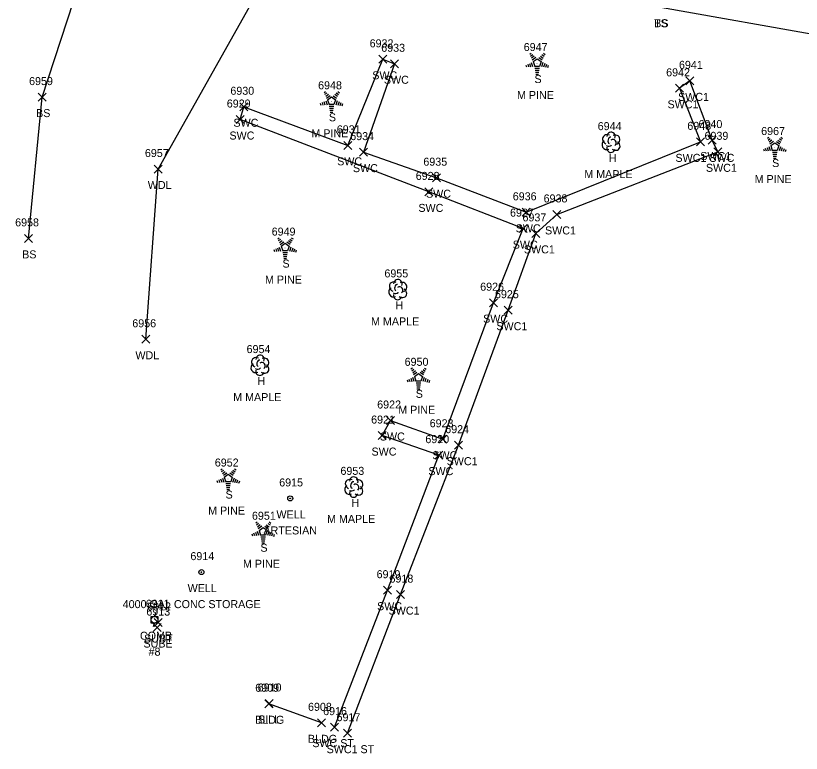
# Model space of a CAD drawing. Extents: x 1678863 to 1683592, y 407783 to 418211.
# Drawn here: x 1680420 to 1680616.3, y 408813.2 to 408997.5 of the extents above; entities that cross this region are included whole.
import ezdxf

# ---------------------------------------------------------------- set-up
doc = ezdxf.new("R2010")
doc.units = 0
for name, color, linetype in [('L_A', 7, 'Continuous'), ('L_C', 7, 'Continuous'), ('L_I', 7, 'Continuous'), ('L_TIC', 7, 'Continuous'), ('LAWA', 7, 'Continuous'), ('LBC', 7, 'Continuous'), ('LELB', 7, 'Continuous'), ('LTC', 7, 'Continuous'), ('LTD', 7, 'Continuous'), ('R_A', 7, 'Continuous'), ('R_I', 7, 'Continuous'), ('R_TIC', 7, 'Continuous'), ('RSW', 7, 'Continuous'), ('U_A', 7, 'Continuous'), ('U_C', 7, 'Continuous'), ('U_I', 7, 'Continuous'), ('U_TIC', 7, 'Continuous'), ('UP', 7, 'Continuous'), ('UWW', 7, 'Continuous')]:
    doc.layers.add(name, color=color, linetype=linetype)

msp = doc.modelspace()

# ---------------------------------------------------------------- linework, layer by layer
at = {"layer": 'L_TIC'}
for points in [[(1680425.67, 408976.2), (1680427.67, 408978.2)], [(1680427.67, 408976.2), (1680425.67, 408978.2)], [(1680454.61, 408958.22), (1680456.61, 408960.22)], [(1680456.61, 408958.22), (1680454.61, 408960.22)], [(1680422.19, 408940.88), (1680424.19, 408942.88)], [(1680424.19, 408940.88), (1680422.19, 408942.88)], [(1680451.51, 408915.66), (1680453.51, 408917.66)], [(1680453.51, 408915.66), (1680451.51, 408917.66)], [(1680482.26, 408824.55), (1680484.26, 408826.55)], [(1680484.26, 408824.55), (1680482.26, 408826.55)], [(1680482.32, 408824.63), (1680484.32, 408826.63)], [(1680484.32, 408824.63), (1680482.32, 408826.63)], [(1680495.45, 408819.79), (1680497.45, 408821.79)], [(1680497.45, 408819.79), (1680495.45, 408821.79)]]:
    msp.add_lwpolyline(points, dxfattribs=at)
at = {"layer": 'LAWA'}
msp.add_lwpolyline([(1680452.51, 408916.66), (1680455.61, 408959.22), (1680491.22, 409022.49)], dxfattribs=at)
at = {"layer": 'LBC'}
msp.add_lwpolyline([(1680496.45, 408820.79), (1680483.26, 408825.55)], dxfattribs=at)
at = {"layer": 'LELB'}
for points in [[(1680581.13, 408999.66), (1680622.52, 408992.36), (1680648.86, 408995.44), (1680697.24, 409002.73), (1680736.42, 409011.41), (1680777.65, 409017.22)], [(1680423.19, 408941.88), (1680426.67, 408977.2), (1680439.17, 409015.64)]]:
    msp.add_lwpolyline(points, dxfattribs=at)
at = {"layer": 'LTC'}
for p, q in [((1680548.46, 408987.92), (1680548.82, 408988.18)), ((1680548.67, 408987.45), (1680549.2, 408987.84)), ((1680548.88, 408986.99), (1680549.58, 408987.5)), ((1680549.09, 408986.52), (1680549.97, 408987.16)), ((1680549.31, 408986.07), (1680550.33, 408986.8)), ((1680550.33, 408986.8), (1680551.32, 408986.08)), ((1680550.75, 408987.12), (1680551.56, 408986.53)), ((1680551.12, 408987.46), (1680551.8, 408986.97)), ((1680551.49, 408987.81), (1680552.04, 408987.41)), ((1680551.86, 408988.16), (1680552.28, 408987.86)), ((1680547.49, 408985.2), (1680547.65, 408984.73)), ((1680547.95, 408985.42), (1680548.16, 408984.76)), ((1680548.4, 408985.63), (1680548.68, 408984.8)), ((1680548.86, 408985.85), (1680549.19, 408984.83)), ((1680549.31, 408986.07), (1680549.7, 408984.87)), ((1680550.93, 408984.87), (1680549.7, 408984.87)), ((1680550.89, 408984.37), (1680549.75, 408984.37)), ((1680551.32, 408986.08), (1680550.93, 408984.87)), ((1680551.76, 408985.81), (1680551.42, 408984.77)), ((1680552.21, 408985.56), (1680551.92, 408984.67)), ((1680552.65, 408985.31), (1680552.41, 408984.58)), ((1680553.09, 408985.06), (1680552.91, 408984.48)), ((1680550.81, 408983.87), (1680549.82, 408983.87)), ((1680550.73, 408983.37), (1680549.89, 408983.37)), ((1680550.64, 408982.87), (1680549.97, 408982.87)), ((1680497.08, 408978.36), (1680497.43, 408978.62)), ((1680500.48, 408978.6), (1680500.9, 408978.29)), ((1680497.29, 408977.89), (1680497.82, 408978.28)), ((1680497.5, 408977.43), (1680498.2, 408977.94)), ((1680497.71, 408976.96), (1680498.59, 408977.6)), ((1680497.93, 408976.51), (1680498.94, 408977.24)), ((1680497.93, 408976.51), (1680498.32, 408975.31)), ((1680498.94, 408977.24), (1680499.94, 408976.52)), ((1680499.36, 408977.55), (1680500.17, 408976.96)), ((1680499.94, 408976.52), (1680499.55, 408975.31)), ((1680499.73, 408977.9), (1680500.41, 408977.41)), ((1680500.11, 408978.25), (1680500.65, 408977.85)), ((1680496.11, 408975.64), (1680496.26, 408975.17)), ((1680496.57, 408975.85), (1680496.78, 408975.2)), ((1680497.02, 408976.07), (1680497.29, 408975.24)), ((1680497.48, 408976.29), (1680497.81, 408975.27)), ((1680499.55, 408975.31), (1680498.32, 408975.31)), ((1680499.51, 408974.81), (1680498.37, 408974.81)), ((1680500.38, 408976.24), (1680500.04, 408975.21)), ((1680500.82, 408975.99), (1680500.53, 408975.11)), ((1680501.27, 408975.74), (1680501.03, 408975.01)), ((1680501.71, 408975.49), (1680501.52, 408974.92)), ((1680499.43, 408974.31), (1680498.44, 408974.31)), ((1680499.34, 408973.81), (1680498.51, 408973.81)), ((1680499.26, 408973.31), (1680498.58, 408973.31)), ((1680607.84, 408966.92), (1680608.19, 408967.17)), ((1680608.05, 408966.45), (1680608.58, 408966.84)), ((1680610.87, 408966.81), (1680611.41, 408966.41)), ((1680611.24, 408967.16), (1680611.66, 408966.85)), ((1680608.24, 408964.85), (1680608.57, 408963.83)), ((1680608.26, 408965.99), (1680608.96, 408966.5)), ((1680608.47, 408965.52), (1680609.35, 408966.16)), ((1680608.69, 408965.06), (1680609.7, 408965.8)), ((1680608.69, 408965.06), (1680609.08, 408963.87)), ((1680609.7, 408965.8), (1680610.7, 408965.07)), ((1680610.12, 408966.11), (1680610.93, 408965.52)), ((1680610.7, 408965.07), (1680610.31, 408963.87)), ((1680610.49, 408966.46), (1680611.17, 408965.97)), ((1680611.14, 408964.8), (1680610.8, 408963.76)), ((1680606.87, 408964.2), (1680607.02, 408963.73)), ((1680607.33, 408964.41), (1680607.54, 408963.76)), ((1680607.78, 408964.63), (1680608.05, 408963.79)), ((1680610.31, 408963.87), (1680609.08, 408963.87)), ((1680610.27, 408963.37), (1680609.13, 408963.37)), ((1680610.19, 408962.87), (1680609.2, 408962.87)), ((1680611.58, 408964.55), (1680611.29, 408963.67)), ((1680612.03, 408964.3), (1680611.79, 408963.57)), ((1680612.47, 408964.05), (1680612.28, 408963.48)), ((1680610.1, 408962.37), (1680609.27, 408962.37)), ((1680610.02, 408961.87), (1680609.34, 408961.87)), ((1680485.49, 408941.79), (1680485.85, 408942.05)), ((1680485.7, 408941.32), (1680486.23, 408941.71)), ((1680485.91, 408940.86), (1680486.62, 408941.37)), ((1680488.15, 408941.33), (1680488.83, 408940.84)), ((1680488.52, 408941.68), (1680489.07, 408941.28)), ((1680488.89, 408942.03), (1680489.31, 408941.73)), ((1680484.98, 408939.29), (1680485.19, 408938.63)), ((1680485.44, 408939.5), (1680485.71, 408938.67)), ((1680485.89, 408939.72), (1680486.22, 408938.7)), ((1680486.12, 408940.39), (1680487, 408941.03)), ((1680486.35, 408939.94), (1680487.36, 408940.67)), ((1680486.35, 408939.94), (1680486.73, 408938.74)), ((1680487.36, 408940.67), (1680488.35, 408939.95)), ((1680487.78, 408940.98), (1680488.59, 408940.4)), ((1680488.35, 408939.95), (1680487.96, 408938.74)), ((1680488.79, 408939.68), (1680488.45, 408938.64)), ((1680489.24, 408939.43), (1680488.95, 408938.54)), ((1680484.53, 408939.07), (1680484.68, 408938.6)), ((1680487.96, 408938.74), (1680486.73, 408938.74)), ((1680487.93, 408938.24), (1680486.78, 408938.24)), ((1680487.84, 408937.74), (1680486.85, 408937.74)), ((1680487.76, 408937.24), (1680486.93, 408937.24)), ((1680489.68, 408939.18), (1680489.44, 408938.45)), ((1680490.13, 408938.93), (1680489.94, 408938.35)), ((1680487.67, 408936.74), (1680487, 408936.74)), ((1680518.79, 408909.24), (1680519.14, 408909.49)), ((1680519, 408908.77), (1680519.53, 408909.15)), ((1680519.21, 408908.3), (1680519.91, 408908.82)), ((1680519.42, 408907.84), (1680520.29, 408908.48)), ((1680519.64, 408907.38), (1680520.65, 408908.12)), ((1680520.65, 408908.12), (1680521.65, 408907.39)), ((1680521.07, 408908.43), (1680521.88, 408907.84)), ((1680521.44, 408908.78), (1680522.12, 408908.29)), ((1680521.81, 408909.13), (1680522.36, 408908.73)), ((1680522.19, 408909.48), (1680522.61, 408909.17)), ((1680517.82, 408906.51), (1680517.97, 408906.05)), ((1680518.28, 408906.73), (1680518.49, 408906.08)), ((1680518.73, 408906.95), (1680519, 408906.11)), ((1680519.19, 408907.16), (1680519.52, 408906.15)), ((1680519.64, 408907.38), (1680520.03, 408906.19)), ((1680521.26, 408906.19), (1680520.03, 408906.19)), ((1680521.65, 408907.39), (1680521.26, 408906.19)), ((1680522.09, 408907.12), (1680521.75, 408906.08)), ((1680522.53, 408906.87), (1680522.24, 408905.99)), ((1680522.98, 408906.62), (1680522.74, 408905.89)), ((1680523.42, 408906.37), (1680523.23, 408905.8)), ((1680521.22, 408905.69), (1680520.08, 408905.69)), ((1680521.14, 408905.19), (1680520.15, 408905.19)), ((1680521.05, 408904.69), (1680520.22, 408904.69)), ((1680520.97, 408904.19), (1680520.29, 408904.19)), ((1680471.27, 408884.06), (1680471.63, 408884.31)), ((1680474.67, 408884.3), (1680475.09, 408883.99)), ((1680471.48, 408883.59), (1680472.01, 408883.97)), ((1680471.69, 408883.12), (1680472.39, 408883.64)), ((1680471.9, 408882.66), (1680472.78, 408883.3)), ((1680472.12, 408882.2), (1680473.14, 408882.94)), ((1680473.14, 408882.94), (1680474.13, 408882.21)), ((1680473.56, 408883.25), (1680474.37, 408882.66)), ((1680473.93, 408883.6), (1680474.61, 408883.11)), ((1680474.3, 408883.95), (1680474.85, 408883.55)), ((1680470.3, 408881.33), (1680470.46, 408880.87)), ((1680470.76, 408881.55), (1680470.97, 408880.9)), ((1680471.21, 408881.77), (1680471.49, 408880.93)), ((1680471.67, 408881.98), (1680472, 408880.97)), ((1680472.12, 408882.2), (1680472.51, 408881.01)), ((1680473.74, 408881.01), (1680472.51, 408881.01)), ((1680473.7, 408880.51), (1680472.56, 408880.51)), ((1680474.13, 408882.21), (1680473.74, 408881.01)), ((1680474.57, 408881.94), (1680474.23, 408880.9)), ((1680475.02, 408881.69), (1680474.73, 408880.81)), ((1680475.46, 408881.44), (1680475.22, 408880.71)), ((1680475.9, 408881.19), (1680475.72, 408880.62)), ((1680473.62, 408880.01), (1680472.63, 408880.01)), ((1680473.54, 408879.51), (1680472.7, 408879.51)), ((1680473.45, 408879.01), (1680472.78, 408879.01)), ((1680479.98, 408870.75), (1680480.34, 408871.01)), ((1680480.19, 408870.29), (1680480.72, 408870.67)), ((1680483.01, 408870.65), (1680483.56, 408870.25)), ((1680483.38, 408870.99), (1680483.8, 408870.69)), ((1680480.38, 408868.68), (1680480.71, 408867.66)), ((1680480.4, 408869.82), (1680481.1, 408870.33)), ((1680480.61, 408869.36), (1680481.49, 408869.99)), ((1680480.83, 408868.9), (1680481.85, 408869.64)), ((1680480.83, 408868.9), (1680481.22, 408867.71)), ((1680481.85, 408869.64), (1680482.84, 408868.91)), ((1680482.27, 408869.95), (1680483.08, 408869.36)), ((1680482.84, 408868.91), (1680482.45, 408867.71)), ((1680482.64, 408870.3), (1680483.32, 408869.8)), ((1680483.28, 408868.64), (1680482.94, 408867.6)), ((1680479.01, 408868.03), (1680479.17, 408867.57)), ((1680479.47, 408868.25), (1680479.68, 408867.6)), ((1680479.92, 408868.47), (1680480.2, 408867.63)), ((1680482.45, 408867.71), (1680481.22, 408867.71)), ((1680482.41, 408867.21), (1680481.27, 408867.21)), ((1680482.33, 408866.71), (1680481.34, 408866.71)), ((1680483.72, 408868.39), (1680483.44, 408867.51)), ((1680484.17, 408868.14), (1680483.93, 408867.41)), ((1680484.61, 408867.89), (1680484.43, 408867.32)), ((1680482.25, 408866.21), (1680481.41, 408866.21)), ((1680482.16, 408865.71), (1680481.49, 408865.71))]:
    msp.add_line(p, q, dxfattribs=at)
at = {"layer": 'LTD'}
for p, q in [((1680568.75, 408965.94), (1680568.75, 408965.94)), ((1680568.75, 408965.94), (1680568.75, 408965.94)), ((1680515.46, 408929.13), (1680515.46, 408929.13)), ((1680515.46, 408929.13), (1680515.46, 408929.13)), ((1680481.02, 408910.21), (1680481.02, 408910.21)), ((1680481.02, 408910.21), (1680481.02, 408910.21)), ((1680504.47, 408879.77), (1680504.47, 408879.77)), ((1680504.47, 408879.77), (1680504.47, 408879.77))]:
    msp.add_line(p, q, dxfattribs=at)
for centre in [(1680568.8, 408967.38), (1680515.51, 408930.56), (1680481.07, 408911.65), (1680504.51, 408881.2)]:
    msp.add_arc(centre, 1.05, 335.5272, 180.9563, dxfattribs=at)
for centre, major_axis, ratio, start_param, end_param in [((1680567.96, 408966.61), (1.21, -0.51), 0.895232, 1.570796, 4.712389), ((1680568.54, 408966.4), (-0.208, -0.792), 0.645439, 3.141593, 6.283185), ((1680569.25, 408965.78), (-0.5, 0.667), 0.989748, 3.141593, 6.283185), ((1680569.79, 408966.53), (-1.14, -0.48), 0.949671, 1.570796, 4.712389), ((1680567.67, 408965.24), (0.58, -1.04), 0.959034, 3.141593, 6.283185), ((1680568.29, 408965.19), (-0.625, -0.083), 0.423636, 0, 3.141593), ((1680569.75, 408965.11), (-1.09, 0.79), 0.841452, 1.570796, 4.712389), ((1680568.75, 408964.44), (0.26, 1.06), 0.942809, 1.570796, 4.712389), ((1680514.38, 408928.42), (0.58, -1.04), 0.959034, 3.141593, 6.283185), ((1680514.67, 408929.8), (1.21, -0.51), 0.895232, 1.570796, 4.712389), ((1680515.25, 408929.59), (-0.208, -0.792), 0.645439, 3.141593, 6.283185), ((1680515.96, 408928.96), (-0.5, 0.667), 0.989748, 3.141593, 6.283185), ((1680516.5, 408929.71), (-1.14, -0.48), 0.949671, 1.570796, 4.712389), ((1680515.46, 408927.63), (0.26, 1.06), 0.942809, 1.570796, 4.712389), ((1680515, 408928.38), (-0.625, -0.083), 0.423636, 0, 3.141593), ((1680516.46, 408928.3), (-1.09, 0.79), 0.841452, 1.570796, 4.712389), ((1680480.23, 408910.88), (1.21, -0.51), 0.895232, 1.570796, 4.712389), ((1680482.06, 408910.79), (-1.14, -0.48), 0.949671, 1.570796, 4.712389), ((1680479.94, 408909.5), (0.58, -1.04), 0.959034, 3.141593, 6.283185), ((1680480.81, 408910.67), (-0.208, -0.792), 0.645439, 3.141593, 6.283185), ((1680481.52, 408910.04), (-0.5, 0.667), 0.989748, 3.141593, 6.283185), ((1680482.02, 408909.38), (-1.09, 0.79), 0.841452, 1.570796, 4.712389), ((1680481.02, 408908.71), (0.26, 1.06), 0.942809, 1.570796, 4.712389), ((1680480.56, 408909.46), (-0.625, -0.083), 0.423636, 0, 3.141593), ((1680503.67, 408880.43), (1.21, -0.51), 0.895232, 1.570796, 4.712389), ((1680504.26, 408880.22), (-0.208, -0.792), 0.645439, 3.141593, 6.283185), ((1680504.97, 408879.6), (-0.5, 0.667), 0.989748, 3.141593, 6.283185), ((1680505.51, 408880.35), (-1.14, -0.48), 0.949671, 1.570796, 4.712389), ((1680503.38, 408879.06), (0.58, -1.04), 0.959034, 3.141593, 6.283185), ((1680504.47, 408878.27), (0.26, 1.06), 0.942809, 1.570796, 4.712389), ((1680504.01, 408879.02), (-0.625, -0.083), 0.423636, 0, 3.141593), ((1680505.47, 408878.93), (-1.09, 0.79), 0.841452, 1.570796, 4.712389)]:
    msp.add_ellipse(centre, major_axis=major_axis, ratio=ratio, start_param=start_param, end_param=end_param, dxfattribs=at)
at = {"layer": 'R_TIC'}
for points in [[(1680510.76, 408985.64), (1680512.76, 408987.64)], [(1680512.76, 408985.64), (1680510.76, 408987.64)], [(1680513.65, 408984.53), (1680515.65, 408986.53)], [(1680515.65, 408984.53), (1680513.65, 408986.53)], [(1680587.49, 408980.26), (1680589.49, 408982.26)], [(1680589.49, 408980.26), (1680587.49, 408982.26)], [(1680584.86, 408978.39), (1680586.86, 408980.39)], [(1680586.86, 408978.39), (1680584.86, 408980.39)], [(1680476.06, 408973.78), (1680478.06, 408975.78)], [(1680478.06, 408973.78), (1680476.06, 408975.78)], [(1680475.07, 408970.59), (1680477.07, 408972.59)], [(1680477.07, 408970.59), (1680475.07, 408972.59)], [(1680590.14, 408965.01), (1680592.14, 408967.01)], [(1680592.14, 408965.01), (1680590.14, 408967.01)], [(1680590.14, 408965.01), (1680592.14, 408967.01)], [(1680592.14, 408965.01), (1680590.14, 408967.01)], [(1680593.03, 408965.46), (1680595.03, 408967.46)], [(1680595.03, 408965.46), (1680593.03, 408967.46)], [(1680501.99, 408964.14), (1680503.99, 408966.14)], [(1680503.99, 408964.14), (1680501.99, 408966.14)], [(1680505.91, 408962.44), (1680507.91, 408964.44)], [(1680507.91, 408962.44), (1680505.91, 408964.44)], [(1680594.45, 408962.52), (1680596.45, 408964.52)], [(1680596.45, 408962.52), (1680594.45, 408964.52)], [(1680524.19, 408956.05), (1680526.19, 408958.05)], [(1680526.19, 408956.05), (1680524.19, 408958.05)], [(1680522.28, 408952.5), (1680524.28, 408954.5)], [(1680524.28, 408952.5), (1680522.28, 408954.5)], [(1680546.59, 408947.4), (1680548.59, 408949.4)], [(1680548.59, 408947.4), (1680546.59, 408949.4)], [(1680554.24, 408946.87), (1680556.24, 408948.87)], [(1680556.24, 408946.87), (1680554.24, 408948.87)], [(1680545.85, 408943.32), (1680547.85, 408945.32)], [(1680547.85, 408943.32), (1680545.85, 408945.32)], [(1680548.96, 408942.13), (1680550.96, 408944.13)], [(1680550.96, 408942.13), (1680548.96, 408944.13)], [(1680538.44, 408924.8), (1680540.44, 408926.8)], [(1680540.44, 408924.8), (1680538.44, 408926.8)], [(1680542.09, 408922.93), (1680544.09, 408924.93)], [(1680544.09, 408922.93), (1680542.09, 408924.93)], [(1680512.65, 408895.36), (1680514.65, 408897.36)], [(1680514.65, 408895.36), (1680512.65, 408897.36)], [(1680510.57, 408891.59), (1680512.57, 408893.59)], [(1680512.57, 408891.59), (1680510.57, 408893.59)], [(1680525.77, 408890.67), (1680527.77, 408892.67)], [(1680527.77, 408890.67), (1680525.77, 408892.67)], [(1680529.66, 408889.19), (1680531.66, 408891.19)], [(1680531.66, 408889.19), (1680529.66, 408891.19)], [(1680524.77, 408886.7), (1680526.77, 408888.7)], [(1680526.77, 408886.7), (1680524.77, 408888.7)], [(1680511.95, 408852.94), (1680513.95, 408854.94)], [(1680513.95, 408852.94), (1680511.95, 408854.94)], [(1680515.16, 408851.84), (1680517.16, 408853.84)], [(1680517.16, 408851.84), (1680515.16, 408853.84)], [(1680498.64, 408818.71), (1680500.64, 408820.71)], [(1680500.64, 408818.71), (1680498.64, 408820.71)], [(1680501.93, 408817.2), (1680503.93, 408819.2)], [(1680503.93, 408817.2), (1680501.93, 408819.2)]]:
    msp.add_lwpolyline(points, dxfattribs=at)
at = {"layer": 'RSW'}
for points in [[(1680499.64, 408819.71), (1680512.95, 408853.94), (1680525.77, 408887.7), (1680511.57, 408892.59), (1680513.65, 408896.36), (1680526.77, 408891.67), (1680539.44, 408925.8), (1680546.85, 408944.32), (1680523.28, 408953.5), (1680476.07, 408971.59), (1680477.06, 408974.78), (1680502.99, 408965.14), (1680511.76, 408986.64), (1680514.65, 408985.53), (1680506.91, 408963.44), (1680525.19, 408957.05), (1680547.59, 408948.4), (1680591.14, 408966.01)], [(1680502.93, 408818.2), (1680516.16, 408852.84), (1680530.66, 408890.19), (1680543.09, 408923.93), (1680549.96, 408943.13), (1680555.24, 408947.87), (1680595.45, 408963.52), (1680594.03, 408966.46), (1680588.49, 408981.26), (1680585.86, 408979.39), (1680591.14, 408966.01)]]:
    msp.add_lwpolyline(points, dxfattribs=at)
at = {"layer": 'U_TIC'}
for points in [[(1680454.4, 408843.6), (1680456.4, 408845.6)], [(1680456.4, 408843.6), (1680454.4, 408845.6)], [(1680454.62, 408844.87), (1680456.62, 408846.87)], [(1680456.62, 408844.87), (1680454.62, 408846.87)]]:
    msp.add_lwpolyline(points, dxfattribs=at)
at = {"layer": 'UP'}
for p, q in [((1680453.85, 408845.73), (1680453.85, 408847.4)), ((1680453.85, 408847.4), (1680455.52, 408847.4)), ((1680454.93, 408848.23), (1680454.68, 408847.4)), ((1680455.52, 408847.4), (1680455.52, 408845.73)), ((1680455.52, 408845.73), (1680453.85, 408845.73)), ((1680454.43, 408844.9), (1680454.68, 408845.73)), ((1680454.68, 408846.56), (1680454.68, 408846.56))]:
    msp.add_line(p, q, dxfattribs=at)
msp.add_circle((1680454.68, 408846.56), 0.833, dxfattribs=at)
at = {"layer": 'UWW'}
for centre, radius in [((1680488.6, 408876.88), 0.625), ((1680488.6, 408876.88), 0.0833), ((1680466.41, 408858.46), 0.625), ((1680466.41, 408858.46), 0.0833)]:
    msp.add_circle(centre, radius, dxfattribs=at)

# ---------------------------------------------------------------- texts
at = {"layer": 'L_A'}
for s, p in [('TS', (1680579.54, 408994.66)), ('TS', (1680579.54, 408994.66)), ('BS', (1680579.57, 408994.66)), ('S', (1680549.65, 408980.71)), ('BS', (1680425.11, 408972.2)), ('S', (1680498.27, 408971.15)), ('H', (1680568.19, 408960.94)), ('S', (1680609.03, 408959.71)), ('WDL', (1680453.02, 408954.22)), ('BS', (1680421.63, 408936.88)), ('S', (1680486.68, 408934.58)), ('H', (1680514.89, 408924.13)), ('WDL', (1680449.93, 408911.66)), ('H', (1680480.45, 408905.21)), ('S', (1680519.98, 408902.03)), ('S', (1680472.46, 408876.85)), ('H', (1680503.9, 408874.77)), ('S', (1680481.17, 408863.55)), ('BLDG', (1680479.85, 408820.55)), ('SILL', (1680480.58, 408820.63)), ('BLDG', (1680493.04, 408815.79))]:
    msp.add_text(s, height=2, dxfattribs=at).set_placement(p)
at = {"layer": 'L_C'}
for s, p in [('M PINE', (1680545.29, 408976.71)), ('M PINE', (1680493.91, 408967.15)), ('M MAPLE', (1680562.11, 408956.94)), ('M PINE', (1680604.67, 408955.71)), ('M PINE', (1680482.32, 408930.58)), ('M MAPLE', (1680508.81, 408920.13)), ('M MAPLE', (1680474.37, 408901.21)), ('M PINE', (1680515.62, 408898.03)), ('M PINE', (1680468.1, 408872.85)), ('M MAPLE', (1680497.82, 408870.77)), ('M PINE', (1680476.81, 408859.55))]:
    msp.add_text(s, height=2, dxfattribs=at).set_placement(p)
at = {"layer": 'L_I'}
for s, p in [('6947', (1680546.96, 408988.71)), ('6959', (1680423.36, 408980.2)), ('6948', (1680495.58, 408979.15)), ('6944', (1680565.45, 408968.94)), ('6967', (1680606.29, 408967.71)), ('6957', (1680452.3, 408962.22)), ('6958', (1680419.88, 408944.88)), ('6949', (1680483.98, 408942.58)), ('6955', (1680512.15, 408932.13)), ('6956', (1680449.15, 408919.66)), ('6954', (1680477.71, 408913.21)), ('6950', (1680517.2, 408910.03)), ('6952', (1680469.77, 408884.85)), ('6953', (1680501.16, 408882.77)), ('6951', (1680479.05, 408871.55)), ('6909', (1680479.87, 408828.55)), ('6910', (1680480.49, 408828.63)), ('6908', (1680493.06, 408823.79))]:
    msp.add_text(s, height=2, dxfattribs=at).set_placement(p)
at = {"layer": 'LTC'}
for p in [(1680550.21, 408985.82), (1680498.83, 408976.25), (1680609.59, 408964.81), (1680487.24, 408939.69), (1680520.54, 408907.13), (1680473.02, 408881.95), (1680481.73, 408868.65)]:
    msp.add_text('.', height=1.04, rotation=270, dxfattribs=at).set_placement(p)
at = {"layer": 'R_A'}
for s, p in [('SWC', (1680509.12, 408981.64)), ('SWC', (1680512.02, 408980.53)), ('SWC1', (1680585.53, 408976.26)), ('SWC1', (1680582.9, 408974.39)), ('SWC', (1680474.42, 408969.78)), ('SWC', (1680473.43, 408966.59)), ('SWC1 SWC', (1680584.88, 408961.01)), ('SWC1 SWC', (1680584.88, 408961.01)), ('SWC1', (1680591.07, 408961.46)), ('SWC', (1680500.35, 408960.14)), ('SWC', (1680504.28, 408958.44)), ('SWC1', (1680592.49, 408958.52)), ('SWC', (1680522.55, 408952.05)), ('SWC', (1680520.64, 408948.5)), ('SWC', (1680544.95, 408943.4)), ('SWC1', (1680552.28, 408942.87)), ('SWC', (1680544.21, 408939.32)), ('SWC1', (1680547, 408938.13)), ('SWC', (1680536.81, 408920.8)), ('SWC1', (1680540.13, 408918.93)), ('SWC', (1680511.01, 408891.36)), ('SWC', (1680508.93, 408887.59)), ('SWC', (1680524.13, 408886.67)), ('SWC1', (1680527.7, 408885.19)), ('SWC', (1680523.13, 408882.7)), ('SWC', (1680510.31, 408848.94)), ('SWC1', (1680513.2, 408847.84)), ('SWC ST', (1680494.13, 408814.71)), ('SWC1 ST', (1680497.71, 408813.2))]:
    msp.add_text(s, height=2, dxfattribs=at).set_placement(p)
at = {"layer": 'R_I'}
for s, p in [('6932', (1680508.46, 408989.64)), ('6933', (1680511.35, 408988.53)), ('6942', (1680582.55, 408982.39)), ('6941', (1680585.75, 408984.26)), ('6930', (1680473.66, 408977.78)), ('6929', (1680472.76, 408974.59)), ('6943', (1680587.84, 408969.01)), ('6943', (1680587.84, 408969.01)), ('6940', (1680590.64, 408969.46)), ('6931', (1680500.25, 408968.14)), ('6934', (1680503.61, 408966.44)), ('6939', (1680592.14, 408966.52)), ('6935', (1680521.88, 408960.05)), ('6928', (1680519.97, 408956.5)), ('6936', (1680544.22, 408951.4)), ('6938', (1680551.93, 408950.87)), ('6927', (1680543.54, 408947.32)), ('6937', (1680546.65, 408946.13)), ('6926', (1680536.08, 408928.8)), ('6925', (1680539.78, 408926.93)), ('6922', (1680510.34, 408899.36)), ('6921', (1680508.83, 408895.59)), ('6923', (1680523.46, 408894.67)), ('6924', (1680527.35, 408893.19)), ('6920', (1680522.38, 408890.7)), ('6919', (1680510.2, 408856.94)), ('6918', (1680513.42, 408855.84)), ('6916', (1680496.84, 408822.71)), ('6917', (1680500.19, 408821.2))]:
    msp.add_text(s, height=2, dxfattribs=at).set_placement(p)
at = {"layer": 'U_A'}
for s, p in [('WELL', (1680485.17, 408871.88)), ('WELL', (1680462.98, 408853.46)), ('COMB', (1680451.07, 408841.56)), ('SUBE', (1680451.94, 408839.6)), ('SUBT', (1680452.11, 408840.87))]:
    msp.add_text(s, height=2, dxfattribs=at).set_placement(p)
at = {"layer": 'U_C'}
for s, p in [('ARTESIAN', (1680481.93, 408867.88)), ('4000 GAL CONC STORAGE', (1680446.76, 408849.46)), ('#8', (1680453.22, 408837.56))]:
    msp.add_text(s, height=2, dxfattribs=at).set_placement(p)
at = {"layer": 'U_I'}
for s, p in [('6915', (1680485.86, 408879.88)), ('6914', (1680463.67, 408861.46)), ('6911', (1680452.51, 408849.56)), ('6912', (1680452.88, 408848.87)), ('6913', (1680452.66, 408847.6))]:
    msp.add_text(s, height=2, dxfattribs=at).set_placement(p)

doc.saveas('drawing.dxf')
